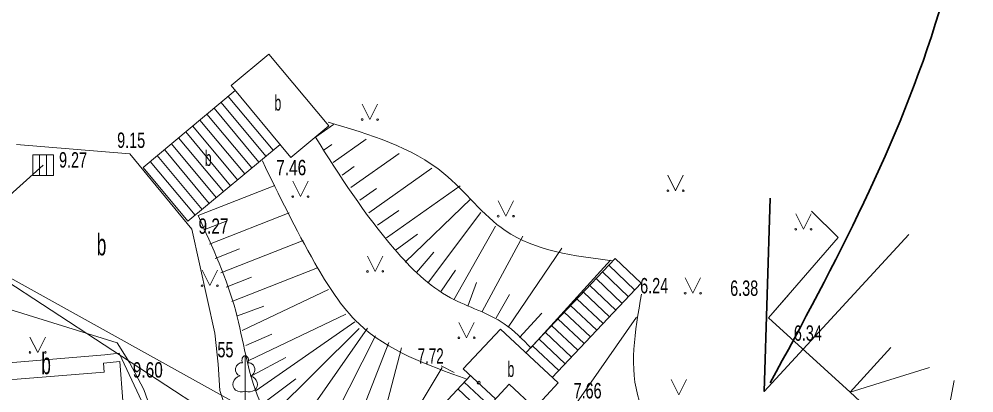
# Model space of a CAD drawing. Extents: x 514052 to 514314, y 297701 to 297876.
# Drawn here: x 514240.99 to 514272.02, y 297814.23 to 297826.38 of the extents above; entities that cross this region are included whole.
import ezdxf
from ezdxf.enums import TextEntityAlignment as Align

# ---------------------------------------------------------------- set-up
doc = ezdxf.new("R2010")
doc.units = 0
doc.header["$LTSCALE"] = 0.2
for name, color, linetype, lineweight in [('1', 7, 'Continuous', 13), ('2', 7, 'Continuous', 13), ('28', 7, 'Continuous', 13), ('3', 7, 'Continuous', 13), ('5', 7, 'Continuous', 13), ('56', 7, 'Continuous', 13), ('59', 7, 'Continuous', 13), ('6', 7, 'Continuous', 13), ('60', 7, 'Continuous', 13), ('62', 7, 'Continuous', 13), ('63', 7, 'Continuous', 13)]:
    doc.layers.add(name, color=color, linetype=linetype, lineweight=lineweight)
for name, color, linetype in [('10', 7, 'Continuous'), ('12', 7, 'Continuous'), ('15', 7, 'Continuous'), ('32', 7, 'Continuous'), ('8', 7, 'Continuous')]:
    doc.layers.add(name, color=color, linetype=linetype)

msp = doc.modelspace()

# ---------------------------------------------------------------- linework, layer by layer
at = {"layer": '1'}
for p, q in [((514250.62, 297822.541), (514251.205, 297822.955)), ((514250.908, 297822.133), (514251.157, 297822.308)), ((514251.197, 297821.724), (514252.271, 297822.483)), ((514251.773, 297820.907), (514253.337, 297822.012)), ((514251.485, 297821.316), (514251.881, 297821.595)), ((514252.35, 297820.091), (514254.403, 297821.54)), ((514246.808, 297819.997), (514249.304, 297820.977)), ((514252.927, 297819.274), (514255.324, 297820.967)), ((514252.062, 297820.499), (514252.604, 297820.882)), ((514253.538, 297818.484), (514255.667, 297820.538)), ((514247.173, 297819.066), (514249.764, 297820.083)), ((514252.639, 297819.682), (514253.325, 297820.167)), ((514254.294, 297817.831), (514255.998, 297820.1)), ((514246.991, 297819.532), (514247.754, 297819.831)), ((514253.216, 297818.866), (514253.934, 297819.391)), ((514255.116, 297817.261), (514256.477, 297819.651)), ((514247.539, 297818.135), (514250.224, 297819.19)), ((514256.039, 297816.881), (514257.363, 297819.323)), ((514247.356, 297818.601), (514248.147, 297818.912)), ((514253.903, 297818.142), (514254.472, 297818.807)), ((514256.886, 297816.365), (514258.627, 297818.933)), ((514257.626, 297815.693), (514260.213, 297818.546)), ((514247.904, 297817.205), (514250.682, 297818.295)), ((514254.701, 297817.54), (514255.171, 297818.221)), ((514247.722, 297817.67), (514248.541, 297817.992)), ((514248.233, 297816.261), (514251.042, 297817.589)), ((514255.569, 297817.052), (514255.857, 297817.822)), ((514256.493, 297816.673), (514256.924, 297817.427)), ((514248.085, 297816.738), (514248.942, 297817.048)), ((514248.458, 297815.287), (514251.603, 297816.793)), ((514257.009, 297810.908), (514261.061, 297816.697)), ((514257.256, 297816.029), (514257.982, 297816.83)), ((514248.694, 297814.315), (514251.9, 297816.544)), ((514249.074, 297813.393), (514252.04, 297816.325)), ((514249.742, 297812.659), (514252.315, 297816.334)), ((514248.352, 297815.775), (514249.202, 297816.138)), ((514250.674, 297812.337), (514252.57, 297816.091)), ((514251.664, 297812.448), (514253.007, 297815.873)), ((514252.629, 297812.711), (514253.412, 297815.701)), ((514248.567, 297814.799), (514249.654, 297815.389)), ((514253.544, 297813.069), (514254.738, 297815.061)), ((514248.854, 297813.842), (514249.982, 297814.687))]:
    msp.add_line(p, q, dxfattribs=at)
for points in [[(514250.62, 297822.541), (514253.185, 297818.91), (514255.013, 297817.326), (514256.759, 297816.48), (514257.632, 297815.688)], [(514246.808, 297819.997), (514248.029, 297816.887), (514248.799, 297813.988), (514249.977, 297812.519), (514251.8, 297812.481), (514253.078, 297812.852), (514253.566, 297813.059), (514253.864, 297812.892)]]:
    msp.add_spline(points, degree=3, dxfattribs=at)
at = {"layer": '2'}
for points in [[(514265.349, 297816.673), (514267.617, 297819.286), (514266.745, 297820.143)], [(514268.002, 297814.257), (514265.349, 297816.673), (514266.012, 297817.437)]]:
    msp.add_lwpolyline(points, dxfattribs=at)
at = {"layer": '28'}
for p, q in [((514241.652, 297821.976), (514241.652, 297821.301)), ((514241.877, 297821.976), (514241.877, 297821.301))]:
    msp.add_line(p, q, dxfattribs=at)
msp.add_lwpolyline([(514241.427, 297821.976), (514242.102, 297821.976), (514242.102, 297821.301), (514241.427, 297821.301)], close=True, dxfattribs=at)
at = {"layer": '3'}
for p in [(514260.171, 297807.171), (514264.293, 297802.389)]:
    msp.add_line(p, (514238.829, 297819.008), dxfattribs=at)
msp.add_lwpolyline([(514241.765, 297821.638), (514238.829, 297819.008), (514236.773, 297820.161)], dxfattribs=at)
at = {"layer": '5'}
for p, q in [((514248.335, 297815.443), (514248.335, 297814.29)), ((514248.425, 297815.211), (514248.424, 297815.212)), ((514248.335, 297814.29), (514248.335, 297813.943))]:
    msp.add_line(p, q, dxfattribs=at)
for points in [[(514252.139, 297823.618), (514252.389, 297823.118), (514252.639, 297823.618)], [(514262.077, 297821.307), (514262.327, 297820.807), (514262.577, 297821.307)], [(514249.881, 297821.113), (514250.131, 297820.613), (514250.381, 297821.113)], [(514256.56, 297820.478), (514256.81, 297819.978), (514257.06, 297820.478)], [(514266.233, 297820.051), (514266.483, 297819.551), (514266.733, 297820.051)], [(514252.31, 297818.683), (514252.56, 297818.183), (514252.81, 297818.683)], [(514246.934, 297818.219), (514247.184, 297817.719), (514247.434, 297818.219)], [(514262.638, 297817.972), (514262.888, 297817.472), (514263.138, 297817.972)], [(514255.284, 297816.526), (514255.534, 297816.026), (514255.784, 297816.526)], [(514241.34, 297816.048), (514241.59, 297815.548), (514241.84, 297816.048)], [(514262.185, 297814.673), (514262.435, 297814.173), (514262.685, 297814.673)]]:
    msp.add_lwpolyline(points, dxfattribs=at)
for centre, radius in [((514252.1388, 297823.1176), 0.028), ((514252.6388, 297823.1176), 0.0263), ((514249.8807, 297820.6126), 0.028), ((514250.3807, 297820.6126), 0.0263), ((514262.0766, 297820.8068), 0.028), ((514262.5766, 297820.8068), 0.0263), ((514256.5597, 297819.978), 0.028), ((514257.0597, 297819.978), 0.0263), ((514266.2331, 297819.5509), 0.028), ((514266.7331, 297819.5509), 0.0263), ((514252.3093, 297818.1827), 0.028), ((514252.8093, 297818.1827), 0.0263), ((514246.9337, 297817.7185), 0.028), ((514247.4337, 297817.7185), 0.0263), ((514262.6379, 297817.4712), 0.028), ((514263.1379, 297817.4712), 0.0263), ((514255.2836, 297816.0257), 0.028), ((514255.7836, 297816.0257), 0.0263), ((514241.3394, 297815.5478), 0.028), ((514241.8394, 297815.5478), 0.0263)]:
    msp.add_circle(centre, radius, dxfattribs=at)
for centre, major_axis, ratio, start_param, end_param in [((514248.3354, 297815.2932), (0, -0.1499), 0.707107, 3.1453698, 5.2874846), ((514248.3345, 297815.2932), (0, -0.1499), 0.707107, 0.9957007, 3.1378155), ((514248.2067, 297814.9984), (-0.0387, -0.2124), 0.861323, 3.1415927, 6.2831853), ((514248.4632, 297814.9984), (0.0387, -0.2124), 0.861323, 6.2831853, 9.424778), ((514248.2454, 297814.5361), (0.3068, 0.0951), 0.814445, 1.5707963, 4.7520146), ((514248.4245, 297814.5361), (-0.3068, 0.0951), 0.814445, 1.5311707, 4.712389)]:
    msp.add_ellipse(centre, major_axis=major_axis, ratio=ratio, start_param=start_param, end_param=end_param, dxfattribs=at)
at = {"layer": '56'}
for p, q in [((514247.784, 297823.869), (514249.241, 297822.12)), ((514247.323, 297823.485), (514248.78, 297821.736)), ((514247.553, 297823.677), (514249.01, 297821.928)), ((514247.092, 297823.293), (514248.549, 297821.544)), ((514246.631, 297822.909), (514248.088, 297821.16)), ((514246.862, 297823.101), (514248.319, 297821.352)), ((514246.17, 297822.525), (514247.627, 297820.776)), ((514246.401, 297822.717), (514247.858, 297820.968)), ((514245.94, 297822.333), (514247.397, 297820.584)), ((514245.479, 297821.949), (514246.936, 297820.2)), ((514245.709, 297822.141), (514247.166, 297820.392)), ((514245.248, 297821.757), (514246.705, 297820.008)), ((514257.458, 297815.537), (514260.359, 297818.6)), ((514261.209, 297817.795), (514260.359, 297818.6)), ((514260.796, 297817.359), (514259.946, 297818.164)), ((514261.003, 297817.577), (514260.153, 297818.382)), ((514260.59, 297817.142), (514259.74, 297817.947)), ((514258.314, 297814.738), (514261.209, 297817.795)), ((514260.384, 297816.924), (514259.534, 297817.729)), ((514259.971, 297816.488), (514259.121, 297817.293)), ((514260.178, 297816.706), (514259.328, 297817.511)), ((514259.765, 297816.27), (514258.915, 297817.075)), ((514259.352, 297815.835), (514258.502, 297816.64)), ((514259.559, 297816.052), (514258.709, 297816.857)), ((514255.425, 297815.017), (514256.632, 297816.309)), ((514256.632, 297816.309), (514258.51, 297814.555)), ((514259.146, 297815.617), (514258.296, 297816.422)), ((514258.734, 297815.181), (514257.884, 297815.986)), ((514258.94, 297815.399), (514258.09, 297816.204)), ((514258.527, 297814.963), (514257.677, 297815.768)), ((514255.658, 297814.799), (514253.815, 297812.826)), ((514255.425, 297815.017), (514256.473, 297814.038)), ((514254.63, 297812.065), (514256.916, 297814.512)), ((514255.453, 297814.58), (514256.268, 297813.819)), ((514257.747, 297813.737), (514256.916, 297814.512)), ((514257.747, 297813.737), (514258.51, 297814.555)), ((514255.248, 297814.361), (514256.063, 297813.6))]:
    msp.add_line(p, q, dxfattribs=at)
msp.add_lwpolyline([(514249.106, 297825.248), (514247.878, 297824.225), (514249.823, 297821.89), (514251.051, 297822.912)], close=True, dxfattribs=at)
msp.add_lwpolyline([(514248.014, 297824.061), (514245.018, 297821.565), (514246.475, 297819.816), (514249.471, 297822.312)], dxfattribs=at)
at = {"layer": '59'}
msp.add_lwpolyline([(514244.841, 297807.586), (514244.258, 297815.252), (514243.73, 297815.203), (514243.754, 297814.91), (514237.815, 297814.426), (514237.791, 297814.715), (514236.224, 297814.594)], dxfattribs=at)
at = {"layer": '6'}
msp.add_circle((514255.9289, 297814.5621), 0.05, dxfattribs=at)
at = {"layer": '60'}
for p, q in [((514268.002, 297814.257), (514270.576, 297815.058)), ((514271.387, 297814.634), (514270.812, 297811.651))]:
    msp.add_line(p, q, dxfattribs=at)
msp.add_lwpolyline([(514270.812, 297811.651), (514268.002, 297814.257), (514269.323, 297815.711)], dxfattribs=at)
at = {"layer": '62'}
msp.add_line((514254.703, 297815.116), (514255.125, 297814.893), dxfattribs=at)
for points in [[(514251.029, 297823.032), (514254.795, 297821.367), (514256.787, 297819.51), (514260.279, 297818.528)], [(514255.539, 297814.684), (514252.037, 297816.476), (514250.603, 297818.453), (514248.895, 297821.772)], [(514261.218, 297817.439), (514261.146, 297813.983), (514262.948, 297811.354), (514263.993, 297809.986)]]:
    msp.add_spline(points, degree=3, dxfattribs=at)
at = {"layer": '63'}
for points in [[(514253.566, 297813.059), (514252.471, 297812.479), (514251.559, 297811.997), (514250.65, 297811.6), (514249.672, 297811.695), (514248.671, 297812.423), (514247.79, 297813.464), (514247.508, 297814.306), (514247.455, 297815.172), (514247.348, 297816.179), (514246.601, 297819.558), (514244.582, 297822.003), (514240.904, 297822.303)], [(514246.215, 297808.465), (514245.37, 297813.427), (514245.042, 297814.341), (514244.571, 297815.22), (514244.17, 297815.861), (514235.94, 297818.419)], [(514240.249, 297815.183), (514243.772, 297815.47), (514244.241, 297815.523), (514244.979, 297813.95), (514245.467, 297807.986)]]:
    msp.add_lwpolyline(points, dxfattribs=at)
at = {"layer": '63', "lineweight": 35}
msp.add_lwpolyline([(514265.404, 297820.56), (514265.208, 297814.281), (514269.914, 297819.383)], dxfattribs=at)
msp.add_spline([(514205.891, 297851.931), (514208.984, 297845.601), (514211.9, 297843.132), (514220.108, 297842.416), (514230.817, 297844.853), (514239.226, 297848.988), (514250.207, 297849.381), (514260.992, 297845.947), (514267.168, 297841.238), (514271.678, 297833.39), (514270.894, 297826.621), (514265.404, 297814.555)], degree=3, dxfattribs=at)

# ---------------------------------------------------------------- texts
at = {"layer": '10', "width": 0.6}
for p in [(514243.6655, 297818.703), (514241.8635, 297814.84)]:
    msp.add_text('b', height=0.7, dxfattribs=at).set_placement(p, align=Align.CENTER)
at = {"layer": '12', "width": 0.7}
msp.add_text('55', height=0.5, dxfattribs=at).set_placement((514247.434, 297815.39))
at = {"layer": '15', "width": 0.6}
for p in [(514249.285, 297823.411), (514247.022, 297821.61), (514256.861, 297814.753)]:
    msp.add_text('b', height=0.5, dxfattribs=at).set_placement(p)
at = {"layer": '32', "width": 0.7}
msp.add_text('9.27', height=0.5, dxfattribs=at).set_placement((514242.284, 297821.558))
at = {"layer": '8'}
for s, width, p in [(' 9.15', 0.7, (514244.043, 297822.197)), (' 7.46', 0.75, (514249.204, 297821.309)), (' 9.27', 0.75, (514246.678, 297819.405)), ('6.24', 0.7, (514261.175, 297817.469)), ('6.38', 0.7, (514264.101, 297817.388)), ('6.34', 0.7, (514266.171, 297815.928)), ('7.72', 0.65, (514253.942, 297815.185)), (' 9.60', 0.75, (514244.542, 297814.731)), ('7.66', 0.7, (514259.01, 297814.055))]:
    msp.add_text(s, height=0.5, dxfattribs=dict(at, width=width)).set_placement(p)

doc.saveas('drawing.dxf')
